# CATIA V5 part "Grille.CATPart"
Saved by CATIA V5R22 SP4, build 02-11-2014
Part number: Grille
Material "ﾌﾟﾗｽﾃｨｯｸ": density 1200 kg/m3, Young's modulus 2.2e+09 Pa, Poisson ratio 0.38, thermal expansion 6.84e-05 1/K
Bounding box of the stored display mesh (mm): x -185 to -100.001, y -313 to 313, z 227 to 413
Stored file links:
  C:\DATA\Car_ASSY\教育モデル\5_ASM\FIN\Grille.CATPart
  C:\DATA\Car_ASSY\Car_Assy_1210\Grille_1210.CATPart
  C:\DATA\Car_ASSY\Car_Assy_1210\Grille.CATPart
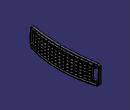
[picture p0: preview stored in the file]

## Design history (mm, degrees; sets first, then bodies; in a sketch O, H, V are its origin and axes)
Set1 "Front"
  Point1: (-1100, 0, 300)
  Circle1: type CtrRad, Start -30, End 30, Center Point1, Support xy-plane, Radius 1000, FirstDirection (1, 0, 0)
  Circle2: type CtrRad, Start 165, End 195, Center Point1, Support zx-plane, Radius 1000, FirstDirection (-1, 0, 0)
  Sweep1: type Unspec, Profile Circle2, Guide Circle1
Set2 "Danmen"
  Intersect1: ToIntersect1 Sweep1, ToIntersect2 Pad3
  Plane1: type Offset, RefPlane yz-plane, Offset 185, reversed
Body1 (main body)
  Body2
    Pad1: profile Intersect1, direction along X axis reversed, length 20
    Fillet1: radius 2, on face of Pad1
    Sketch1 on Plane1, origin (-185, 0, 0), H (0, 1, 0), V (0, 0, 1)
      circle A1 centre (280, 370) radius 9
      point P1 (280, 370)
      circle A2 centre (280, 370) radius 6
      circle A3 centre (280, 260) radius 9
      circle A4 centre (280, 260) radius 6
      circle A5 centre (-280, 370) radius 9
      circle A6 centre (-280, 370) radius 6
      circle A7 centre (-280, 260) radius 9
      circle A8 centre (-280, 260) radius 6
      radius A1 = 9
      radius A2 = 6
      distance H P1 = 370
      distance P1 V = 280
    Pad2: profile Sketch1, direction (1, 0, 0), up to the existing solid (limit type 2)
  Add1: tool Body2
Body3
  Sketch2 on yz-plane, origin (0, 0, 0), H (0, 1, 0), V (0, 0, 1)
    point P1 (0.0002, 410)
    construction line L1 (0.0002, 410) -> (310, 410)
    point P2 (310, 410)
    line L2 (310, 372.6426) -> (310, 250)
    point P3 (310, 230)
    line L3 (290, 230) -> (0, 230)
    point P4 (0, 230)
    circle A1 centre (280, 370) radius 8
    circle A2 centre (280, 260) radius 8
    spline S1 through (0.0002, 410) (184.2802, 403.8794) (310, 390)
    arc A3 centre (290, 250) radius 20 from (290, 230) to (310, 250) ccw
    point P5 (290, 230)
    point P6 (310, 250)
    arc A4 centre (290, 372.6426) radius 20 from (292.7155, 392.4574) to (310, 372.6426) cw
    point P8 (292.7155, 392.4574)
    point P9 (310, 372.6426)
    offsetcurve C1
    point P11 (0.0002, 390)
    point P12 (290.0001, 372.6425)
    construction line L4 (0.0002, 410) -> (0.0002, 390)
    point P13 (0.0002, 410)
    construction line L5 through (0.0002, 410) direction (-1, 0)
    construction line L6 (292.7155, 392.4574) -> (290.0001, 372.6425)
    construction line L7 through (292.7155, 392.4574) direction (0.9907, -0.1358)
    line L8 (260, 376.4843) -> (260, 255)
    point P14 (257.373, 372.6426)
    point P15 (257.373, 250)
    construction line L9 (310, 372.6426) -> (257.373, 372.6426)
    construction line L10 (310, 250) -> (257.373, 250)
    line L11 (255, 250) -> (0, 250)
    point P16 (290, 250)
    point P17 (0, 250)
    construction line L12 (290, 230) -> (290, 250)
    construction line L13 (0, 230) -> (0, 250)
    point P18 (260, 376.4843)
    point P19 (260, 250)
    line L14 (272, 370) -> (260, 370)
    point P20 (272, 370)
    point P21 (260, 370)
    line L15 (288, 370) -> (310, 370)
    point P22 (288, 370)
    point P23 (310, 370)
    line L16 (288, 260) -> (310, 260)
    point P24 (288, 260)
    point P25 (310, 260)
    line L17 (272, 260) -> (260, 260)
    point P26 (272, 260)
    point P27 (260, 260)
    line L18 (260, 275) -> (0, 275)
    point P28 (260, 275)
    point P29 (0, 275)
    construction line L19 (260, 250) -> (260, 275)
    construction line L20 (0, 250) -> (0, 275)
    line L21 (260, 300) -> (0, 300)
    point P30 (260, 300)
    point P31 (0, 300)
    construction line L22 (260, 275) -> (260, 300)
    construction line L23 (0, 275) -> (0, 300)
    line L24 (260, 325) -> (0, 325)
    point P32 (260, 325)
    point P33 (0, 325)
    construction line L25 (260, 300) -> (260, 325)
    construction line L26 (0, 300) -> (0, 325)
    line L27 (260, 350) -> (0, 350)
    point P34 (260, 350)
    point P35 (0, 350)
    construction line L28 (260, 325) -> (260, 350)
    construction line L29 (0, 325) -> (0, 350)
    line L30 (260, 375) -> (0, 375)
    point P36 (260, 375)
    point P37 (0, 375)
    construction line L31 (260, 350) -> (260, 375)
    construction line L32 (0, 350) -> (0, 375)
    arc A5 centre (255, 255) radius 5 from (260, 255) to (255, 250) cw
    point P38 (260, 255)
    point P39 (255, 250)
    line L33 (17.5, 250) -> (17.5, 389.9532)
    point P41 (17.5, 250)
    point P42 (17.5, 389.9532)
    line L34 (52.5, 250) -> (52.5, 389.5709)
    point P43 (52.5, 250)
    point P44 (52.5, 389.5709)
    line L35 (87.5, 250) -> (87.5, 388.769)
    point P45 (87.5, 250)
    point P46 (87.5, 388.769)
    line L36 (122.5, 250) -> (122.5, 387.4859)
    point P47 (122.5, 250)
    point P48 (122.5, 387.4859)
    line L37 (157.5, 250) -> (157.5, 385.6484)
    point P49 (157.5, 250)
    point P50 (157.5, 385.6484)
    line L38 (192.5, 250) -> (192.5, 383.1854)
    point P51 (192.5, 250)
    point P52 (192.5, 383.1854)
    line L39 (227.5, 250) -> (227.5, 380.0419)
    point P53 (227.5, 250)
    point P54 (227.5, 380.0419)
    point P55 (-0.0002, 410)
    point P56 (-310, 410)
    construction line L40 (-0.0002, 410) -> (-310, 410)
    point P57 (-310, 230)
    point P58 (0, 230)
    point P59 (-290, 230)
    point P60 (-310, 250)
    point P62 (-292.7155, 392.4574)
    point P63 (-310, 372.6426)
    point P65 (-0.0002, 390)
    point P66 (-290.0001, 372.6425)
    point P67 (-257.373, 372.6426)
    point P68 (-257.373, 250)
    point P69 (-290, 250)
    point P70 (0, 250)
    point P71 (-260, 376.4843)
    point P72 (-260, 250)
    point P73 (-272, 370)
    point P74 (-260, 370)
    point P75 (-288, 370)
    point P76 (-310, 370)
    point P77 (-288, 260)
    point P78 (-310, 260)
    point P79 (-272, 260)
    point P80 (-260, 260)
    point P81 (-260, 275)
    point P82 (0, 275)
    point P83 (-260, 300)
    point P84 (0, 300)
    point P85 (-260, 325)
    point P86 (0, 325)
    point P87 (-260, 350)
    point P88 (0, 350)
    point P89 (-260, 375)
    point P90 (0, 375)
    point P91 (-260, 255)
    point P92 (-255, 250)
    point P94 (-17.5, 250)
    point P95 (-17.5, 389.9532)
    point P96 (-52.5, 250)
    point P97 (-52.5, 389.5709)
    point P98 (-87.5, 250)
    point P99 (-87.5, 388.769)
    point P100 (-122.5, 250)
    point P101 (-122.5, 387.4859)
    point P102 (-157.5, 250)
    point P103 (-157.5, 385.6484)
    point P104 (-192.5, 250)
    point P105 (-192.5, 383.1854)
    point P106 (-227.5, 250)
    point P107 (-227.5, 380.0419)
    line L41 (-310, 372.6426) -> (-310, 250)
    line L42 (-290, 230) -> (0, 230)
    circle A6 centre (-280, 370) radius 8
    circle A7 centre (-280, 260) radius 8
    spline S2 through (-0.0002, 410) (-184.2802, 403.8794) (-310, 390)
    arc A8 centre (-290, 250) radius 20 from (-290, 230) to (-310, 250) cw
    arc A9 centre (-290, 372.6426) radius 20 from (-292.7155, 392.4574) to (-310, 372.6426) ccw
    offsetcurve C2
    line L43 (-260, 376.4843) -> (-260, 255)
    line L44 (-255, 250) -> (0, 250)
    line L45 (-272, 370) -> (-260, 370)
    line L46 (-288, 370) -> (-310, 370)
    line L47 (-288, 260) -> (-310, 260)
    line L48 (-272, 260) -> (-260, 260)
    line L49 (-260, 275) -> (0, 275)
    line L50 (-260, 300) -> (0, 300)
    line L51 (-260, 325) -> (0, 325)
    line L52 (-260, 350) -> (0, 350)
    line L53 (-260, 375) -> (0, 375)
    arc A10 centre (-255, 255) radius 5 from (-260, 255) to (-255, 250) ccw
    line L54 (-17.5, 250) -> (-17.5, 389.9532)
    line L55 (-52.5, 250) -> (-52.5, 389.5709)
    line L56 (-87.5, 250) -> (-87.5, 388.769)
    line L57 (-122.5, 250) -> (-122.5, 387.4859)
    line L58 (-157.5, 250) -> (-157.5, 385.6484)
    line L59 (-192.5, 250) -> (-192.5, 383.1854)
    line L60 (-227.5, 250) -> (-227.5, 380.0419)
    point P108 (0.0002, 410)
    point P109 (310, 390)
    point P110 (184.2802, 403.8794)
    point P111 (-0.0002, 410)
    point P112 (-310, 390)
    point P113 (-184.2802, 403.8794)
    distance H L3 = 230
    distance L2 V = 310
    distance P109 L1 = 20
    distance P2 P3 = 180
    distance V P110 = 184.2802
    distance P110 P109 V = 13.8794
    distance P108 P4 = 180
    radius A3 = 20
    radius A4 = 20
    distance L2 L8 = 50
    distance L3 L11 = 20
    distance L16 L3 = 30
    distance L15 L16 = 110
    distance A1 L15 = 8
    distance A1 L15 = 8
    distance A1 L2 = 38
    distance A2 L16 = 8
    distance A2 L16 = 8
    distance L2 A2 = 38
    distance L11 L18 = 25
    distance L18 L21 = 25
    distance L21 L24 = 25
    distance L24 L27 = 25
    distance L27 L30 = 25
    radius A5 = 5
    distance V L33 = 17.5
    distance L33 L34 = 35
    distance L34 L35 = 35
    distance L35 L36 = 35
    distance L36 L37 = 35
    distance L37 L38 = 35
    distance L38 L39 = 35
    horizontal: L1 H, L3 H, L14 H, L15 H, L16 H, L17 H
    vertical: L2 V, L33 V, L34 V, L35 V, L36 V, L37 V, L38 V, L39 V
    coincidence: P4 V, P108 P1, P109 L2, P2 L2, L3 P3, L2 P3, P108 P13, P12 C1, P16 L11, P20 A1, P21 L8, P22 L14, P22 A1, P23 L2, P24 A2, P25 L2, P26 L16, P26 A2, P27 L8, L8 P19, L11 P19, P41 L11, P42 C1, P43 L11, P44 C1, P45 L11, P46 C1, P47 L11, P48 C1, P49 L11, P50 C1, P51 L11, P52 C1, P53 L11, P54 C1, P4 P58, P17 P70, P29 P82, P31 P84, P33 P86, P35 P88, P37 P90
    tangency: A3 L3, A3 L2, A4 S1, A4 L2, L5 S1, L7 S1, A5 L8, A5 L11
    perpendicularity: L4 L5, L6 L7, L9 L2, L9 L8, L10 L2, L10 L8, L12 L3, L12 L11, L13 L3, L13 L11, L19 L11, L19 L18, L20 L11, L20 L18, L22 L18, L22 L21, L23 L18, L23 L21, L25 L21, L25 L24, L26 L21, L26 L24, L28 L24, L28 L27, L29 L24, L29 L27, L31 L27, L31 L30, L32 L27, L32 L30
    symmetry: P1 P55 V, P2 P56 V, L1 L40 V, P3 P57 V, P4 P58 V, P5 P59 V, P6 P60 V, P8 P62 V, P9 P63 V, P11 P65 V, P12 P66 V, P14 P67 V, P15 P68 V, P16 P69 V, P17 P70 V, P18 P71 V, P19 P72 V, P20 P73 V, P21 P74 V, P22 P75 V, P23 P76 V, P24 P77 V, P25 P78 V, P26 P79 V, P27 P80 V, P28 P81 V, P29 P82 V, P30 P83 V, P31 P84 V, P32 P85 V, P33 P86 V, P34 P87 V, P35 P88 V, P36 P89 V, P37 P90 V, P38 P91 V, P39 P92 V, P41 P94 V, P42 P95 V, P43 P96 V, P44 P97 V, P45 P98 V, P46 P99 V, P47 P100 V, P48 P101 V, P49 P102 V, P50 P103 V, P51 P104 V, P52 P105 V, P53 P106 V, P54 P107 V, L2 L41 V, L3 L42 V, A1 A6 V, A2 A7 V, S1 S2 V, A3 A8 V, A4 A9 V, C1 C2 V, L8 L43 V, L11 L44 V, L14 L45 V, L15 L46 V, L16 L47 V, L17 L48 V, L18 L49 V, L21 L50 V, L24 L51 V, L27 L52 V, L30 L53 V, A5 A10 V, L33 L54 V, L34 L55 V, L35 L56 V, L36 L57 V, L37 L58 V, L38 L59 V, L39 L60 V, P108 P111 V, P109 P112 V, P110 P113 V
  Pad3: profile Sketch2, direction (-1, 0, 0), length 350, thin wall 6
